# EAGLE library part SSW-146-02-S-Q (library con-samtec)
THROUGH-HOLE .025" SQ POST SOCKET Source: Samtec SSW.pdf
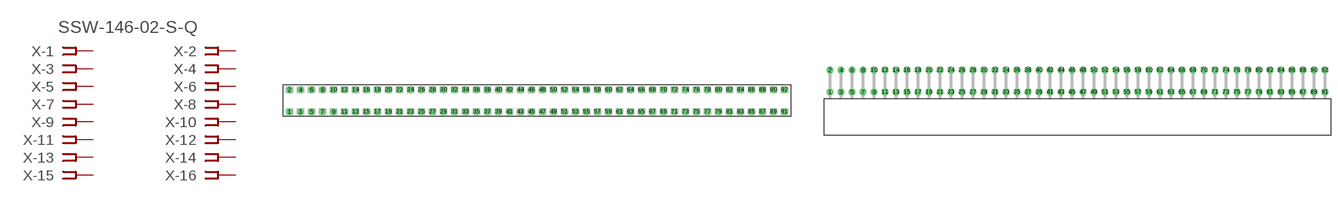
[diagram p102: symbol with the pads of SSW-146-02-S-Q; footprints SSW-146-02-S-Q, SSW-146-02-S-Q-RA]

Designator prefix X; gates -1=FPINV -2=FPIN -3=FPIN -4=FPIN -5=FPIN -6=FPIN -7=FPIN -8=FPIN -9=FPIN -10=FPIN -11=FPIN -12=FPIN -13=FPIN -14=FPIN -15=FPIN -16=FPIN -17=FPIN -18=FPIN -19=FPIN -20=FPIN -21=FPIN -22=FPIN -23=FPIN -24=FPIN -25=FPIN -26=FPIN -27=FPIN -28=FPIN -29=FPIN -30=FPIN -31=FPIN -32=FPIN -33=FPIN -34=FPIN -35=FPIN -36=FPIN -37=FPIN -38=FPIN -39=FPIN -40=FPIN -41=FPIN -42=FPIN -43=FPIN -44=FPIN -45=FPIN -46=FPIN -47=FPIN -48=FPIN -49=FPIN -50=FPIN -51=FPIN -52=FPIN -53=FPIN -54=FPIN -55=FPIN -56=FPIN -57=FPIN -58=FPIN -59=FPIN -60=FPIN -61=FPIN -62=FPIN -63=FPIN -64=FPIN -65=FPIN -66=FPIN -67=FPIN -68=FPIN -69=FPIN -70=FPIN -71=FPIN -72=FPIN -73=FPIN -74=FPIN -75=FPIN -76=FPIN -77=FPIN -78=FPIN -79=FPIN -80=FPIN -81=FPIN -82=FPIN -83=FPIN -84=FPIN -85=FPIN -86=FPIN -87=FPIN -88=FPIN -89=FPIN -90=FPIN -91=FPIN -92=FPIN

## SSW-146-02-S-Q (OC_FARNELL: unknown; OC_NEWARK: unknown)  [SSW-146-02-S-Q]
1  -1:1  pas
2  -2:1  pas
3  -3:1  pas
4  -4:1  pas
5  -5:1  pas
6  -6:1  pas
7  -7:1  pas
8  -8:1  pas
9  -9:1  pas
10  -10:1  pas
11  -11:1  pas
12  -12:1  pas
13  -13:1  pas
14  -14:1  pas
15  -15:1  pas
16  -16:1  pas
17  -17:1  pas
18  -18:1  pas
19  -19:1  pas
20  -20:1  pas
21  -21:1  pas
22  -22:1  pas
23  -23:1  pas
24  -24:1  pas
25  -25:1  pas
26  -26:1  pas
27  -27:1  pas
28  -28:1  pas
29  -29:1  pas
30  -30:1  pas
31  -31:1  pas
32  -32:1  pas
33  -33:1  pas
34  -34:1  pas
35  -35:1  pas
36  -36:1  pas
37  -37:1  pas
38  -38:1  pas
39  -39:1  pas
40  -40:1  pas
41  -41:1  pas
42  -42:1  pas
43  -43:1  pas
44  -44:1  pas
45  -45:1  pas
46  -46:1  pas
47  -47:1  pas
48  -48:1  pas
49  -49:1  pas
50  -50:1  pas
51  -51:1  pas
52  -52:1  pas
53  -53:1  pas
54  -54:1  pas
55  -55:1  pas
56  -56:1  pas
57  -57:1  pas
58  -58:1  pas
59  -59:1  pas
60  -60:1  pas
61  -61:1  pas
62  -62:1  pas
63  -63:1  pas
64  -64:1  pas
65  -65:1  pas
66  -66:1  pas
67  -67:1  pas
68  -68:1  pas
69  -69:1  pas
70  -70:1  pas
71  -71:1  pas
72  -72:1  pas
73  -73:1  pas
74  -74:1  pas
75  -75:1  pas
76  -76:1  pas
77  -77:1  pas
78  -78:1  pas
79  -79:1  pas
80  -80:1  pas
81  -81:1  pas
82  -82:1  pas
83  -83:1  pas
84  -84:1  pas
85  -85:1  pas
86  -86:1  pas
87  -87:1  pas
88  -88:1  pas
89  -89:1  pas
90  -90:1  pas
91  -91:1  pas
92  -92:1  pas

## SSW-146-02-S-QRA (OC_FARNELL: unknown; OC_NEWARK: unknown)  [SSW-146-02-S-Q-RA]
Pads as for SSW-146-02-S-Q

## Footprint SSW-146-02-S-Q (pad centres in mm)
THROUGH-HOLE .025" SQ POST SOCKET Source: Samtec SSW.pdf
drill 1 pad 1.5 octagon: 1 -57.15,-2.54; 2 -57.15,2.54; 3 -54.61,-2.54; 4 -54.61,2.54; 5 -52.07,-2.54; 6 -52.07,2.54; 7 -49.53,-2.54; 8 -49.53,2.54; 9 -46.99,-2.54; 10 -46.99,2.54; 11 -44.45,-2.54; 12 -44.45,2.54; 13 -41.91,-2.54; 14 -41.91,2.54; 15 -39.37,-2.54; 16 -39.37,2.54; 17 -36.83,-2.54; 18 -36.83,2.54; 19 -34.29,-2.54; 20 -34.29,2.54; 21 -31.75,-2.54; 22 -31.75,2.54; 23 -29.21,-2.54; 24 -29.21,2.54; 25 -26.67,-2.54; 26 -26.67,2.54; 27 -24.13,-2.54; 28 -24.13,2.54; 29 -21.59,-2.54; 30 -21.59,2.54; 31 -19.05,-2.54; 32 -19.05,2.54; 33 -16.51,-2.54; 34 -16.51,2.54; 35 -13.97,-2.54; 36 -13.97,2.54; 37 -11.43,-2.54; 38 -11.43,2.54; 39 -8.89,-2.54; 40 -8.89,2.54; 41 -6.35,-2.54; 42 -6.35,2.54; 43 -3.81,-2.54; 44 -3.81,2.54; 45 -1.27,-2.54; 46 -1.27,2.54; 47 1.27,-2.54; 48 1.27,2.54; 49 3.81,-2.54; 50 3.81,2.54; 51 6.35,-2.54; 52 6.35,2.54; 53 8.89,-2.54; 54 8.89,2.54; 55 11.43,-2.54; 56 11.43,2.54; 57 13.97,-2.54; 58 13.97,2.54; 59 16.51,-2.54; 60 16.51,2.54; 61 19.05,-2.54; 62 19.05,2.54; 63 21.59,-2.54; 64 21.59,2.54; 65 24.13,-2.54; 66 24.13,2.54; 67 26.67,-2.54; 68 26.67,2.54; 69 29.21,-2.54; 70 29.21,2.54; 71 31.75,-2.54; 72 31.75,2.54; 73 34.29,-2.54; 74 34.29,2.54; 75 36.83,-2.54; 76 36.83,2.54; 77 39.37,-2.54; 78 39.37,2.54; 79 41.91,-2.54; 80 41.91,2.54; 81 44.45,-2.54; 82 44.45,2.54; 83 46.99,-2.54; 84 46.99,2.54; 85 49.53,-2.54; 86 49.53,2.54; 87 52.07,-2.54; 88 52.07,2.54; 89 54.61,-2.54; 90 54.61,2.54; 91 57.15,-2.54; 92 57.15,2.54

## Footprint SSW-146-02-S-Q-RA (pad centres in mm)
THROUGH-HOLE .025" SQ POST SOCKET Source: Samtec SSW.pdf
drill 1 pad 1.5 octagon: 1 -57.15,1.524; 2 -57.15,6.604; 3 -54.61,1.524; 4 -54.61,6.604; 5 -52.07,1.524; 6 -52.07,6.604; 7 -49.53,1.524; 8 -49.53,6.604; 9 -46.99,1.524; 10 -46.99,6.604; 11 -44.45,1.524; 12 -44.45,6.604; 13 -41.91,1.524; 14 -41.91,6.604; 15 -39.37,1.524; 16 -39.37,6.604; 17 -36.83,1.524; 18 -36.83,6.604; 19 -34.29,1.524; 20 -34.29,6.604; 21 -31.75,1.524; 22 -31.75,6.604; 23 -29.21,1.524; 24 -29.21,6.604; 25 -26.67,1.524; 26 -26.67,6.604; 27 -24.13,1.524; 28 -24.13,6.604; 29 -21.59,1.524; 30 -21.59,6.604; 31 -19.05,1.524; 32 -19.05,6.604; 33 -16.51,1.524; 34 -16.51,6.604; 35 -13.97,1.524; 36 -13.97,6.604; 37 -11.43,1.524; 38 -11.43,6.604; 39 -8.89,1.524; 40 -8.89,6.604; 41 -6.35,1.524; 42 -6.35,6.604; 43 -3.81,1.524; 44 -3.81,6.604; 45 -1.27,1.524; 46 -1.27,6.604; 47 1.27,1.524; 48 1.27,6.604; 49 3.81,1.524; 50 3.81,6.604; 51 6.35,1.524; 52 6.35,6.604; 53 8.89,1.524; 54 8.89,6.604; 55 11.43,1.524; 56 11.43,6.604; 57 13.97,1.524; 58 13.97,6.604; 59 16.51,1.524; 60 16.51,6.604; 61 19.05,1.524; 62 19.05,6.604; 63 21.59,1.524; 64 21.59,6.604; 65 24.13,1.524; 66 24.13,6.604; 67 26.67,1.524; 68 26.67,6.604; 69 29.21,1.524; 70 29.21,6.604; 71 31.75,1.524; 72 31.75,6.604; 73 34.29,1.524; 74 34.29,6.604; 75 36.83,1.524; 76 36.83,6.604; 77 39.37,1.524; 78 39.37,6.604; 79 41.91,1.524; 80 41.91,6.604; 81 44.45,1.524; 82 44.45,6.604; 83 46.99,1.524; 84 46.99,6.604; 85 49.53,1.524; 86 49.53,6.604; 87 52.07,1.524; 88 52.07,6.604; 89 54.61,1.524; 90 54.61,6.604; 91 57.15,1.524; 92 57.15,6.604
